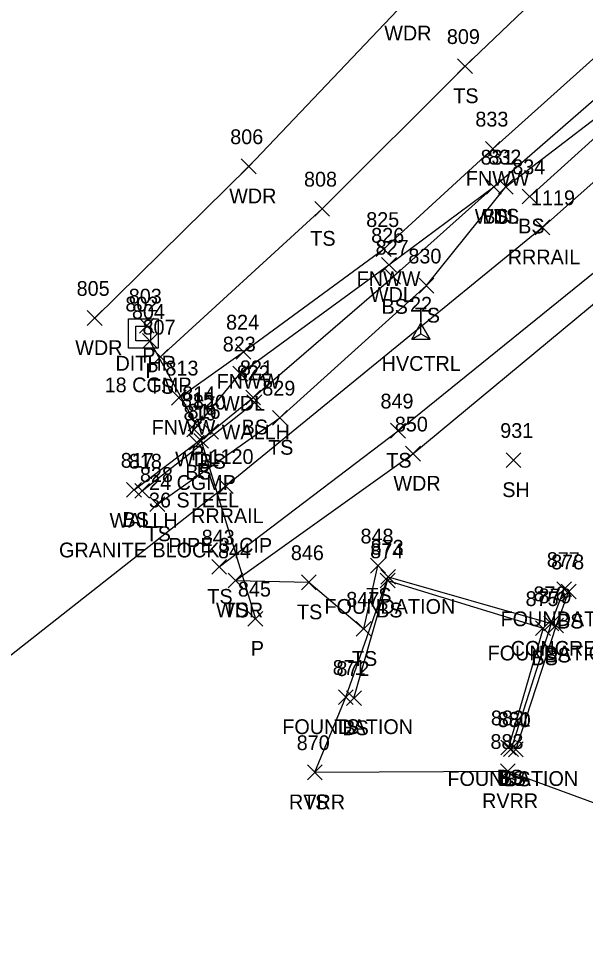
# Model space of a CAD drawing. Extents: x 1764889 to 1767296, y 695936 to 698960.
# Drawn here: x 1766131.8 to 1766208.4, y 696326.9 to 696453.4 of the extents above; entities that cross this region are included whole.
import ezdxf

# ---------------------------------------------------------------- set-up
doc = ezdxf.new("R2010")
doc.units = 0
for name, color, linetype in [('C_A', 7, 'Continuous'), ('C_I', 7, 'Continuous'), ('CPSM', 7, 'Continuous'), ('D_A', 7, 'Continuous'), ('D_C', 7, 'Continuous'), ('D_I', 7, 'Continuous'), ('D_TIC', 7, 'Continuous'), ('DCP', 7, 'Continuous'), ('DHW', 7, 'Continuous'), ('DS', 7, 'Continuous'), ('L_A', 7, 'Continuous'), ('L_C', 7, 'Continuous'), ('L_I', 7, 'Continuous'), ('L_TIC', 7, 'Continuous'), ('LAWA', 7, 'Continuous'), ('LAWE', 7, 'Continuous'), ('LBC', 7, 'Continuous'), ('LELB', 7, 'Continuous'), ('LFNC', 7, 'Continuous'), ('R_A', 7, 'Continuous'), ('R_C', 7, 'Continuous'), ('R_I', 7, 'Continuous'), ('R_TIC', 7, 'Continuous'), ('RR', 7, 'Continuous')]:
    doc.layers.add(name, color=color, linetype=linetype)

msp = doc.modelspace()

# ---------------------------------------------------------------- linework, layer by layer
at = {"layer": 'CPSM'}
for p, q in [((1766184.95, 696410.09), (1766186.2, 696412.26)), ((1766187.45, 696410.09), (1766186.2, 696412.26)), ((1766186.2, 696410.82), (1766186.2, 696412.26)), ((1766184.95, 696410.09), (1766186.2, 696410.82)), ((1766184.95, 696410.09), (1766187.45, 696410.09)), ((1766186.2, 696410.82), (1766186.2, 696410.82)), ((1766186.2, 696410.82), (1766187.45, 696410.09))]:
    msp.add_line(p, q, dxfattribs=at)
at = {"layer": 'D_TIC'}
for points in [[(1766148.14, 696410.92), (1766150.14, 696412.92)], [(1766150.14, 696410.92), (1766148.14, 696412.92)], [(1766148.56, 696408.85), (1766150.56, 696410.85)], [(1766150.56, 696408.85), (1766148.56, 696410.85)], [(1766162.67, 696400.56), (1766164.67, 696402.56)], [(1766164.67, 696400.56), (1766162.67, 696402.56)], [(1766154.71, 696397.72), (1766156.71, 696399.72)], [(1766156.71, 696397.72), (1766154.71, 696399.72)], [(1766155.49, 696395.35), (1766157.49, 696397.35)], [(1766157.49, 696395.35), (1766155.49, 696397.35)], [(1766147.5, 696388.6), (1766149.5, 696390.6)], [(1766149.5, 696388.6), (1766147.5, 696390.6)], [(1766162.81, 696371.3), (1766164.81, 696373.3)], [(1766164.81, 696371.3), (1766162.81, 696373.3)]]:
    msp.add_lwpolyline(points, dxfattribs=at)
at = {"layer": 'DCP'}
for points in [[(1766149.56, 696409.85), (1766155.71, 696398.72)], [(1766156.49, 696396.35), (1766163.81, 696372.3)]]:
    msp.add_lwpolyline(points, dxfattribs=at)
at = {"layer": 'DHW'}
msp.add_lwpolyline([(1766148.5, 696389.6), (1766163.67, 696401.56)], dxfattribs=at)
at = {"layer": 'DS'}
for p, q in [((1766146.65, 696412.87), (1766150.65, 696412.87)), ((1766146.65, 696408.87), (1766146.66, 696412.87)), ((1766150.65, 696412.87), (1766150.65, 696408.87)), ((1766147.65, 696411.87), (1766149.65, 696411.87)), ((1766147.65, 696409.87), (1766147.65, 696411.87)), ((1766149.65, 696411.87), (1766149.65, 696409.87)), ((1766148.65, 696410.88), (1766148.65, 696410.88)), ((1766150.65, 696408.87), (1766146.65, 696408.87)), ((1766149.65, 696409.87), (1766147.65, 696409.87)), ((1766149.15, 696408.87), (1766149.65, 696408.87))]:
    msp.add_line(p, q, dxfattribs=at)
at = {"layer": 'L_TIC'}
for points in [[(1766191.16, 696446.01), (1766193.16, 696448.01)], [(1766193.16, 696446.01), (1766191.16, 696448.01)], [(1766194.92, 696434.85), (1766196.92, 696436.85)], [(1766196.92, 696434.85), (1766194.92, 696436.85)], [(1766161.91, 696432.47), (1766163.91, 696434.47)], [(1766163.91, 696432.47), (1766161.91, 696434.47)], [(1766195.06, 696429.7), (1766197.06, 696431.7)], [(1766197.06, 696429.7), (1766195.06, 696431.7)], [(1766195.06, 696429.7), (1766197.06, 696431.7)], [(1766197.06, 696429.7), (1766195.06, 696431.7)], [(1766196.67, 696429.72), (1766198.67, 696431.72)], [(1766198.67, 696429.72), (1766196.67, 696431.72)], [(1766199.91, 696428.4), (1766201.91, 696430.4)], [(1766201.91, 696428.4), (1766199.91, 696430.4)], [(1766171.83, 696426.73), (1766173.83, 696428.73)], [(1766173.83, 696426.73), (1766171.83, 696428.73)], [(1766180.16, 696421.27), (1766182.16, 696423.27)], [(1766182.16, 696421.27), (1766180.16, 696423.27)], [(1766180.88, 696419.14), (1766182.88, 696421.14)], [(1766182.88, 696419.14), (1766180.88, 696421.14)], [(1766181.43, 696417.53), (1766183.43, 696419.53)], [(1766183.43, 696417.53), (1766181.43, 696419.53)], [(1766185.95, 696416.34), (1766187.95, 696418.34)], [(1766187.95, 696416.34), (1766185.95, 696418.34)], [(1766141.08, 696411.96), (1766143.08, 696413.96)], [(1766143.08, 696411.96), (1766141.08, 696413.96)], [(1766149.99, 696406.72), (1766151.99, 696408.72)], [(1766151.99, 696406.72), (1766149.99, 696408.72)], [(1766161.21, 696407.4), (1766163.21, 696409.4)], [(1766163.21, 696407.4), (1766161.21, 696409.4)], [(1766160.77, 696404.44), (1766162.77, 696406.44)], [(1766162.77, 696404.44), (1766160.77, 696406.44)], [(1766152.45, 696401.19), (1766154.45, 696403.19)], [(1766154.45, 696401.19), (1766152.45, 696403.19)], [(1766162.51, 696401.23), (1766164.51, 696403.23)], [(1766164.51, 696401.23), (1766162.51, 696403.23)], [(1766166.12, 696398.48), (1766168.12, 696400.48)], [(1766168.12, 696398.48), (1766166.12, 696400.48)], [(1766154.54, 696396.9), (1766156.54, 696398.9)], [(1766156.54, 696396.9), (1766154.54, 696398.9)], [(1766156.82, 696396.59), (1766158.82, 696398.59)], [(1766158.82, 696396.59), (1766156.82, 696398.59)], [(1766182.1, 696396.73), (1766184.1, 696398.73)], [(1766184.1, 696396.73), (1766182.1, 696398.73)], [(1766154.89, 696395.12), (1766156.89, 696397.12)], [(1766156.89, 696395.12), (1766154.89, 696397.12)], [(1766184.12, 696393.62), (1766186.12, 696395.62)], [(1766186.12, 696393.62), (1766184.12, 696395.62)], [(1766197.72, 696392.75), (1766199.72, 696394.75)], [(1766199.72, 696392.75), (1766197.72, 696394.75)], [(1766146.4, 696388.72), (1766148.4, 696390.72)], [(1766148.4, 696388.72), (1766146.4, 696390.72)], [(1766149.56, 696386.79), (1766151.56, 696388.79)], [(1766151.56, 696386.79), (1766149.56, 696388.79)], [(1766157.91, 696378.33), (1766159.91, 696380.33)], [(1766159.91, 696378.33), (1766157.91, 696380.33)], [(1766179.39, 696378.48), (1766181.39, 696380.48)], [(1766181.39, 696378.48), (1766179.39, 696380.48)], [(1766160.11, 696376.48), (1766162.11, 696378.48)], [(1766162.11, 696376.48), (1766160.11, 696378.48)], [(1766160.11, 696376.48), (1766162.11, 696378.48)], [(1766162.11, 696376.48), (1766160.11, 696378.48)], [(1766180.7, 696376.48), (1766182.7, 696378.48)], [(1766182.7, 696376.48), (1766180.7, 696378.48)], [(1766180.76, 696376.97), (1766182.76, 696378.97)], [(1766182.76, 696376.97), (1766180.76, 696378.97)], [(1766170.03, 696376.23), (1766172.03, 696378.23)], [(1766172.03, 696376.23), (1766170.03, 696378.23)], [(1766204.58, 696375.3), (1766206.58, 696377.3)], [(1766206.58, 696375.3), (1766204.58, 696377.3)], [(1766205.17, 696374.98), (1766207.17, 696376.98)], [(1766207.17, 696374.98), (1766205.17, 696376.98)], [(1766201.71, 696370.02), (1766203.71, 696372.02)], [(1766203.71, 696370.02), (1766201.71, 696372.02)], [(1766202.83, 696370.67), (1766204.83, 696372.67)], [(1766204.83, 696370.67), (1766202.83, 696372.67)], [(1766202.83, 696370.67), (1766204.83, 696372.67)], [(1766204.83, 696370.67), (1766202.83, 696372.67)], [(1766203.47, 696370.39), (1766205.47, 696372.39)], [(1766205.47, 696370.39), (1766203.47, 696372.39)], [(1766177.46, 696369.93), (1766179.46, 696371.93)], [(1766179.46, 696369.93), (1766177.46, 696371.93)], [(1766175.05, 696360.71), (1766177.05, 696362.71)], [(1766177.05, 696360.71), (1766175.05, 696362.71)], [(1766175.05, 696360.71), (1766177.05, 696362.71)], [(1766177.05, 696360.71), (1766175.05, 696362.71)], [(1766176.14, 696360.56), (1766178.14, 696362.56)], [(1766178.14, 696360.56), (1766176.14, 696362.56)], [(1766197.02, 696353.89), (1766199.02, 696355.89)], [(1766199.02, 696353.89), (1766197.02, 696355.89)], [(1766197.02, 696353.89), (1766199.02, 696355.89)], [(1766199.02, 696353.89), (1766197.02, 696355.89)], [(1766197.38, 696353.7), (1766199.38, 696355.7)], [(1766199.38, 696353.7), (1766197.38, 696355.7)], [(1766197.38, 696353.7), (1766199.38, 696355.7)], [(1766199.38, 696353.7), (1766197.38, 696355.7)], [(1766198.03, 696353.65), (1766200.03, 696355.65)], [(1766200.03, 696353.65), (1766198.03, 696355.65)], [(1766170.85, 696350.54), (1766172.85, 696352.54)], [(1766172.85, 696350.54), (1766170.85, 696352.54)], [(1766170.85, 696350.54), (1766172.85, 696352.54)], [(1766172.85, 696350.54), (1766170.85, 696352.54)], [(1766196.96, 696350.7), (1766198.96, 696352.7)], [(1766198.96, 696350.7), (1766196.96, 696352.7)]]:
    msp.add_lwpolyline(points, dxfattribs=at)
at = {"layer": 'LAWA'}
for points in [[(1766155.54, 696397.9), (1766161.77, 696405.44), (1766181.88, 696420.14), (1766196.06, 696430.7), (1766216.12, 696448.15), (1766224.84, 696455.16), (1766249.96, 696479.46), (1766272.12, 696504.03), (1766288.24, 696524.91), (1766311.88, 696556.72), (1766301.19, 696567.63)], [(1766161.11, 696377.48), (1766185.12, 696394.62), (1766212.55, 696417.35), (1766235.34, 696437.94), (1766256.38, 696458.71), (1766279.26, 696480.23), (1766298.66, 696503.53), (1766311.89, 696514.91), (1766320.79, 696513.88), (1766319.44, 696504.93), (1766321.82, 696491.21)], [(1766142.08, 696412.96), (1766162.91, 696433.47), (1766183.88, 696455.49), (1766203.84, 696482.78)]]:
    msp.add_lwpolyline(points, dxfattribs=at)
at = {"layer": 'LAWE'}
msp.add_lwpolyline([(1766171.85, 696351.54), (1766197.96, 696351.7), (1766219.32, 696343.87), (1766233.88, 696343.92), (1766243.23, 696332.33), (1766235.93, 696325.79)], dxfattribs=at)
at = {"layer": 'LBC'}
for points in [[(1766176.05, 696361.71), (1766181.76, 696377.97), (1766203.83, 696371.67), (1766198.38, 696354.7)], [(1766203.83, 696371.67), (1766205.58, 696376.3)]]:
    msp.add_lwpolyline(points, dxfattribs=at)
at = {"layer": 'LELB'}
for points in [[(1766158.91, 696379.33), (1766183.1, 696397.73), (1766210.95, 696420.2), (1766233.27, 696439.62), (1766253.97, 696460.11), (1766276.48, 696484.28), (1766294.63, 696506.78), (1766322.62, 696540.3)], [(1766150.56, 696387.79), (1766167.12, 696399.48), (1766186.95, 696417.34), (1766197.67, 696430.72), (1766217.09, 696445.57), (1766224.84, 696455.16), (1766252.52, 696476.07), (1766275.69, 696502.98), (1766288.24, 696524.91)], [(1766150.99, 696407.72), (1766172.83, 696427.73), (1766192.16, 696447.01), (1766206.98, 696461.16)], [(1766200.91, 696429.4), (1766217.78, 696444.64), (1766224.84, 696455.16)], [(1766147.4, 696389.72), (1766155.89, 696396.12), (1766157.82, 696397.59), (1766163.51, 696402.23), (1766182.43, 696418.53), (1766196.06, 696430.7)], [(1766161.11, 696377.48), (1766171.03, 696377.23), (1766178.46, 696370.93), (1766180.39, 696379.48)], [(1766177.14, 696361.56), (1766181.7, 696377.48), (1766202.71, 696371.02), (1766198.02, 696354.89)], [(1766206.17, 696375.98), (1766204.47, 696371.39), (1766199.03, 696354.65), (1766198.38, 696354.7), (1766198.02, 696354.89)], [(1766171.85, 696351.54), (1766176.05, 696361.71)]]:
    msp.add_lwpolyline(points, dxfattribs=at)
at = {"layer": 'LFNC'}
msp.add_lwpolyline([(1766153.45, 696402.19), (1766162.21, 696408.4), (1766181.16, 696422.27), (1766195.92, 696435.85), (1766221.63, 696458.93), (1766246.19, 696483.05), (1766268.13, 696505.66), (1766282.49, 696526.8), (1766295.32, 696553.41), (1766299.86, 696566.71)], dxfattribs=at)
at = {"layer": 'R_TIC'}
for points in [[(1766201.65, 696424.22), (1766203.65, 696426.22)], [(1766203.65, 696424.22), (1766201.65, 696426.22)], [(1766158.82, 696389.23), (1766160.82, 696391.23)], [(1766160.82, 696389.23), (1766158.82, 696391.23)]]:
    msp.add_lwpolyline(points, dxfattribs=at)
at = {"layer": 'RR'}
msp.add_lwpolyline([(1766299.86, 696528.94), (1766277.75, 696500.06), (1766257.52, 696477.14), (1766236.01, 696454.81), (1766202.65, 696425.22), (1766159.82, 696390.23), (1766109.4, 696350.61)], dxfattribs=at)

# ---------------------------------------------------------------- texts
at = {"layer": 'C_A'}
msp.add_text('HVCTRL', height=2, dxfattribs=at).set_placement((1766180.89, 696405.82))
at = {"layer": 'C_I'}
msp.add_text('22', height=2, dxfattribs=at).set_placement((1766184.73, 696413.82))
at = {"layer": 'D_A'}
for s, p in [('P', (1766148.51, 696406.92)), ('DITHR', (1766144.9, 696405.85)), ('P', (1766148.94, 696404.85)), ('WALLH', (1766159.26, 696396.56)), ('P', (1766155.09, 696393.72)), ('P', (1766155.87, 696391.35)), ('WALLH', (1766144.09, 696384.6)), ('P', (1766163.19, 696367.3))]:
    msp.add_text(s, height=2, dxfattribs=at).set_placement(p)
at = {"layer": 'D_C'}
for s, p in [('18 CGMP', (1766143.43, 696402.92)), ('24 CGMP', (1766149.44, 696389.72)), ('36 STEEL', (1766149.42, 696387.35)), ('GRANITE BLOCK', (1766137.26, 696380.6))]:
    msp.add_text(s, height=2, dxfattribs=at).set_placement(p)
at = {"layer": 'D_I'}
for s, p in [('803', (1766146.69, 696414.92)), ('802', (1766146.23, 696413.85)), ('804', (1766147.12, 696412.85)), ('822', (1766161.3, 696404.56)), ('814', (1766153.92, 696401.72)), ('816', (1766154.64, 696399.35)), ('818', (1766146.7, 696392.6)), ('845', (1766161.45, 696375.3))]:
    msp.add_text(s, height=2, dxfattribs=at).set_placement(p)
at = {"layer": 'L_A'}
for s, p in [('WDR', (1766181.24, 696450.49)), ('TS', (1766190.57, 696442.01)), ('FNWW', (1766192.27, 696430.85)), ('WDR', (1766160.27, 696428.47)), ('WDL', (1766193.48, 696425.7)), ('BS', (1766194.5, 696425.7)), ('TS', (1766196.08, 696425.72)), ('BS', (1766199.35, 696424.4)), ('TS', (1766171.24, 696422.73)), ('FNWW', (1766177.51, 696417.27)), ('WDL', (1766179.3, 696415.14)), ('BS', (1766180.87, 696413.53)), ('TS', (1766185.36, 696412.34)), ('WDR', (1766139.45, 696407.96)), ('FNWW', (1766158.56, 696403.4)), ('TS', (1766149.4, 696402.72)), ('WDL', (1766159.18, 696400.44)), ('FNWW', (1766149.79, 696397.19)), ('BS', (1766161.95, 696397.23)), ('TS', (1766165.53, 696394.48)), ('WDL', (1766152.96, 696392.9)), ('TS', (1766181.51, 696392.73)), ('BS', (1766156.26, 696392.59)), ('BS', (1766154.33, 696391.12)), ('WDR', (1766182.48, 696389.62)), ('SH', (1766197.2, 696388.75)), ('BS', (1766145.84, 696384.72)), ('TS', (1766148.97, 696382.79)), ('TS', (1766157.32, 696374.33)), ('TS', (1766178.8, 696374.48)), ('WDR', (1766158.48, 696372.48)), ('TS', (1766159.52, 696372.48)), ('FOUNDATION', (1766173.16, 696372.97)), ('BS', (1766180.14, 696372.48)), ('TS', (1766169.44, 696372.23)), ('FOUNDATION', (1766196.97, 696371.3)), ('BS', (1766204.61, 696370.98)), ('FOUNDATION', (1766195.22, 696366.67)), ('FOUNDATION', (1766195.22, 696366.67)), ('BS', (1766202.91, 696366.39)), ('TS', (1766176.87, 696365.93)), ('BS', (1766201.15, 696366.02)), ('FOUNDATION', (1766167.45, 696356.71)), ('TS', (1766174.46, 696356.71)), ('BS', (1766175.58, 696356.56)), ('FOUNDATION', (1766189.78, 696349.7)), ('BS', (1766196.46, 696349.89)), ('BS', (1766196.46, 696349.89)), ('BS', (1766196.82, 696349.7)), ('BS', (1766197.47, 696349.65)), ('RVRR', (1766168.36, 696346.54)), ('TS', (1766170.26, 696346.54)), ('RVRR', (1766194.47, 696346.7))]:
    msp.add_text(s, height=2, dxfattribs=at).set_placement(p)
at = {"layer": 'L_C'}
msp.add_text('CONCRETE', height=2, dxfattribs=at).set_placement((1766198.34, 696367.3))
at = {"layer": 'L_I'}
for s, p in [('809', (1766189.71, 696450.01)), ('833', (1766193.56, 696438.85)), ('806', (1766160.41, 696436.47)), ('831', (1766194.27, 696433.7)), ('831', (1766194.27, 696433.7)), ('832', (1766195.31, 696433.72)), ('834', (1766198.55, 696432.4)), ('808', (1766170.39, 696430.73)), ('825', (1766178.8, 696425.27)), ('826', (1766179.47, 696423.14)), ('827', (1766180.07, 696421.53)), ('830', (1766184.5, 696420.34)), ('805', (1766139.64, 696415.96)), ('807', (1766148.55, 696410.72)), ('824', (1766159.85, 696411.4)), ('823', (1766159.4, 696408.44)), ('813', (1766151.65, 696405.19)), ('821', (1766161.72, 696405.23)), ('829', (1766164.75, 696402.48)), ('815', (1766153.75, 696400.9)), ('820', (1766155.37, 696400.59)), ('849', (1766180.73, 696400.73)), ('819', (1766154.09, 696399.12)), ('850', (1766182.67, 696397.62)), ('931', (1766196.92, 696396.75)), ('817', (1766145.61, 696392.72)), ('828', (1766148.2, 696390.79)), ('843', (1766156.55, 696382.33)), ('848', (1766178.03, 696382.48)), ('844', (1766158.75, 696380.48)), ('844', (1766158.75, 696380.48)), ('846', (1766168.61, 696380.23)), ('874', (1766179.34, 696380.48)), ('873', (1766179.4, 696380.97)), ('877', (1766203.22, 696379.3)), ('878', (1766203.81, 696378.98)), ('847', (1766176.1, 696373.93)), ('875', (1766200.35, 696374.02)), ('876', (1766201.41, 696374.67)), ('876', (1766201.41, 696374.67)), ('879', (1766202.1, 696374.39)), ('871', (1766174.26, 696364.71)), ('871', (1766174.26, 696364.71)), ('872', (1766174.77, 696364.56)), ('882', (1766195.66, 696357.89)), ('882', (1766195.66, 696357.89)), ('881', (1766196.59, 696357.7)), ('881', (1766196.59, 696357.7)), ('880', (1766196.58, 696357.65)), ('870', (1766169.4, 696354.54)), ('870', (1766169.4, 696354.54)), ('883', (1766195.6, 696354.7))]:
    msp.add_text(s, height=2, dxfattribs=at).set_placement(p)
at = {"layer": 'R_A'}
for p in [(1766197.94, 696420.22), (1766155.12, 696385.23)]:
    msp.add_text('RRRAIL', height=2, dxfattribs=at).set_placement(p)
at = {"layer": 'R_C'}
msp.add_text("PIPE 3' CIP", height=2, dxfattribs=at).set_placement((1766152.04, 696381.23))
at = {"layer": 'R_I'}
for s, p in [('1119', (1766201.08, 696428.22)), ('1120', (1766157.61, 696393.23))]:
    msp.add_text(s, height=2, dxfattribs=at).set_placement(p)

doc.saveas('drawing.dxf')
